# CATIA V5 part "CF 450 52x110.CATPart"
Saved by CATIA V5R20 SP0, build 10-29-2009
Part number: CF 450 52x110
Definition: NONE
Nomenclature: CF 450 52x110
Source: Unknown
Description: CF 450 52x110
Bounding box of the stored display mesh (mm): x -39.5 to 39.5, y 0 to 110, z -39.5 to 39.5
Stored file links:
  C:\Users\Utente\Desktop\IO LAVORO\3D X SITO CF\X SITO\CF 450\CF 450 52x110.CATPart
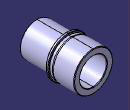
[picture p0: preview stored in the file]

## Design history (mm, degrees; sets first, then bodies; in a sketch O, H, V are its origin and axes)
Body1 "CF 450 52x110" (main body)
  Solid1: solid without history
